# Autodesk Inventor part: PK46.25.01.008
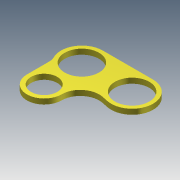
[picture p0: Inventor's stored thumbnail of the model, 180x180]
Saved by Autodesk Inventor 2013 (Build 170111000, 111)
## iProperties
Created: 2005-04
Part Number: PK46.25.01.008
Material: Steel, Mild
Document SubType Name: Modeling
Designer: salex
Manufacturer: Standard
Standards Organization: Custom
Density: 7.86 g/cm^3
Author: salex
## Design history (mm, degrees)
sketch "Эскиз1"
  geometry: L1 (0, 0)-(240, 0); L2 (0, 0)-(0, -180); L3 (-82.5, -180)-(-82.5, -56.513); L4 (0, 100)-(240, 100); L5 (190.906, -91.902)-(219.549, -97.886); C1 r 82 at (0, 0); C2 r 82 at (240, 0); C3 r 62.5 at (0, -180); A1 r 82.5 centre (0, -180) between (-82.5, -180) and (82.5, -180); A2 r 100 centre (0, 0) between (0, 100) and (-82.5, -56.513); A3 r 100 centre (240, 0) between (219.549, -97.886) and (240, 100); A4 r 90 centre (172.5, -180) between (190.906, -91.902) and (82.5, -180)
  constraints: 10 end point, 9 point on circle, 7 centre point, 5 tangent, 3 coincident, 2 equal radius, 1 horizontal, 1 parallel, 1 perpendicular, 1 point on line, 1 other
  dimensions: "d0" = 164 diameter of C1; "d1" = 125 diameter of C3; "d3" = 180 diameter of A4; "d4" = 172.5 distance of A4.centre L2.end; "d5" = 180 vertical distance of A4.centre L1.end; "d6" = 165 diameter of A1; "d7" = 200 diameter of A2; "d8" = 180 distance of C1.centre L2.end; "d9" = 240 distance of C2.centre C1.centre
extrude "Выдавливание1" new body sketch "Эскиз1" distance "d10" = 25; taper "d11" = 0 deg
fillet "Сопряжение1" dims "d12" = 60
body "Solid1"
